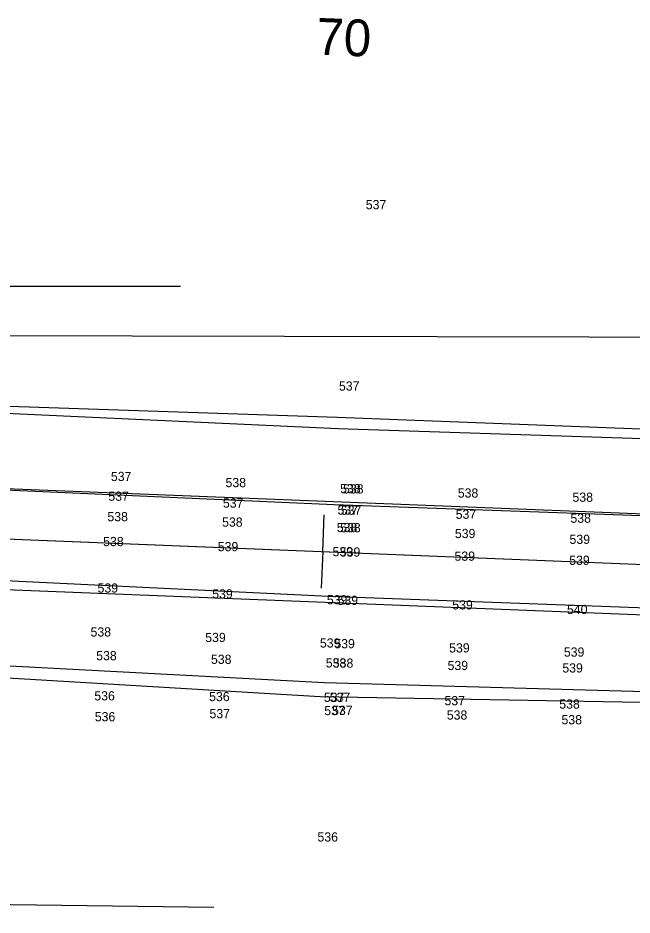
# Model space of a CAD drawing. Extents: x 1787461 to 1970323, y 938412 to 1118748.
# Drawn here: x 1968611.9 to 1968745.6, y 1117839 to 1118034.2 of the extents above; entities that cross this region are included whole.
import ezdxf

# ---------------------------------------------------------------- set-up
doc = ezdxf.new("R2010")
doc.units = 0
for name, color, linetype in [('Default', 7, 'Continuous'), ('HHA ADDITIONAL XSs', 7, 'Continuous'), ('Level 1', 7, 'Continuous'), ('RD_EX_DV_Prop', 7, 'Continuous'), ('RD_EX_Fence_Other', 7, 'Continuous'), ('RD_EX_Road', 7, 'Continuous'), ('RD_EX_VEG', 7, 'Continuous'), ('RD_HC_CL', 7, 'Continuous'), ('RD_HC_Data_Tic', 7, 'Continuous'), ('RD_HC_TX_Sta50', 7, 'Continuous'), ('RD_PD_Final_TrvlWay', 7, 'Continuous')]:
    doc.layers.add(name, color=color, linetype=linetype)

msp = doc.modelspace()

# ---------------------------------------------------------------- linework, layer by layer
at = {"layer": 'HHA ADDITIONAL XSs'}
msp.add_lwpolyline([(1969266.55, 1117963.61), (1967907.56, 1117966.55), (1967403.98, 1117771.66), (1967075.57, 1117641.84)], dxfattribs=at)
at = {"layer": 'Level 1'}
for points in [[(1968647.29, 1117975.82), (1967967.92, 1117975.82), (1967727.47, 1117916.63), (1966985.13, 1117603.01)], [(1968654.57, 1117840.68), (1968058.24, 1117848.48), (1967686.38, 1117740.3), (1966964.76, 1117453.35)]]:
    msp.add_lwpolyline(points, dxfattribs=at)
at = {"layer": 'RD_EX_DV_Prop'}
msp.add_line((1968370.12, 1117930.34), (1969277.79, 1117894.3), dxfattribs=at)
at = {"layer": 'RD_EX_Fence_Other'}
for points in [[(1968536.3, 1117952.23), (1968681.42, 1117947.34), (1968783.46, 1117943.44), (1968890.68, 1117939.26), (1968990.9, 1117933.42), (1969093.99, 1117930.77), (1969190.99, 1117925.01), (1969281.24, 1117923.59)], [(1968579.94, 1117894.82), (1968678.66, 1117889.64), (1968779.4, 1117886.8), (1968885.65, 1117881.12), (1968982.76, 1117877.17), (1969084.96, 1117872.96), (1969186.26, 1117869.55), (1969289.22, 1117863.98)]]:
    msp.add_lwpolyline(points, dxfattribs=at)
at = {"layer": 'RD_EX_Road'}
for points in [[(1968529.31, 1117935.06), (1968680.74, 1117928.37), (1968782, 1117924.72), (1968887.41, 1117920.79), (1968989.99, 1117916.45), (1969090.76, 1117912.42), (1969189.86, 1117908.01), (1969282.04, 1117904.78)], [(1968526.59, 1117915.77), (1968679.57, 1117908.43), (1968780.48, 1117904.73), (1968886.63, 1117901.2), (1968987.42, 1117897.59), (1969088.87, 1117892.19), (1969188.08, 1117888.4), (1969281.71, 1117884.78)]]:
    msp.add_lwpolyline(points, dxfattribs=at)
at = {"layer": 'RD_EX_VEG'}
for points in [[(1968535.19, 1117951.62), (1968681.64, 1117944.89), (1968783.26, 1117941.54), (1968890.11, 1117938.32), (1968991.04, 1117932.18), (1969094.36, 1117929.93), (1969190.81, 1117923.37), (1969281.69, 1117922.69)], [(1968580.4, 1117892.39), (1968677.7, 1117886.58), (1968780.39, 1117884.76), (1968885.66, 1117879.53), (1968982.9, 1117878.1), (1969085.82, 1117874.51), (1969187.45, 1117870.95), (1969289.3, 1117866.04)]]:
    msp.add_lwpolyline(points, dxfattribs=at)
at = {"layer": 'RD_HC_CL'}
msp.add_line((1968119.1, 1117940.3), (1969277.79, 1117894.3), dxfattribs=at)
at = {"layer": 'RD_HC_Data_Tic'}
for q in [(1968678.58, 1117926.1), (1968677.94, 1117910.11)]:
    msp.add_line((1968678.26, 1117918.11), q, dxfattribs=at)
at = {"layer": 'RD_PD_Final_TrvlWay'}
for p, q in [((1968478.85, 1117937.03), (1969278.22, 1117905.3)), ((1968477.98, 1117915.05), (1969277.35, 1117883.31))]:
    msp.add_line(p, q, dxfattribs=at)

# ---------------------------------------------------------------- texts
at = {"layer": 'Default'}
for s, p in [('537', (1968687.63, 1117992.6)), ('537', (1968681.79, 1117953.13)), ('537', (1968632.13, 1117933.45)), ('538', (1968657.09, 1117932.12)), ('538', (1968682.05, 1117930.79)), ('538', (1968682.68, 1117930.75)), ('537', (1968631.57, 1117929.16)), ('538', (1968707.66, 1117929.85)), ('538', (1968732.64, 1117928.94)), ('537', (1968656.52, 1117927.66)), ('538', (1968631.37, 1117924.7)), ('537', (1968681.48, 1117926.15)), ('537', (1968682.22, 1117926.11)), ('537', (1968707.21, 1117925.24)), ('538', (1968656.35, 1117923.52)), ('538', (1968732.19, 1117924.37)), ('538', (1968681.32, 1117922.34)), ('538', (1968682.06, 1117922.3)), ('539', (1968707.03, 1117921.04)), ('538', (1968630.44, 1117919.29)), ('539', (1968731.99, 1117919.77)), ('539', (1968655.41, 1117918.19)), ('539', (1968680.39, 1117917.08)), ('539', (1968681.97, 1117917.01)), ('539', (1968706.95, 1117916.11)), ('539', (1968731.93, 1117915.21)), ('539', (1968629.23, 1117909.18)), ('539', (1968654.19, 1117907.9)), ('539', (1968679.16, 1117906.62)), ('539', (1968681.48, 1117906.5)), ('539', (1968706.46, 1117905.51)), ('540', (1968731.44, 1117904.51)), ('538', (1968627.7, 1117899.62)), ('539', (1968652.67, 1117898.42)), ('539', (1968677.64, 1117897.22)), ('539', (1968680.79, 1117897.07)), ('539', (1968705.78, 1117896.15)), ('538', (1968628.93, 1117894.46)), ('538', (1968653.92, 1117893.67)), ('539', (1968730.76, 1117895.24)), ('538', (1968678.91, 1117892.89)), ('538', (1968680.45, 1117892.84)), ('539', (1968705.44, 1117892.32)), ('539', (1968730.43, 1117891.79)), ('536', (1968628.52, 1117885.72)), ('536', (1968653.52, 1117885.56)), ('537', (1968678.51, 1117885.4)), ('537', (1968679.78, 1117885.39)), ('537', (1968704.77, 1117884.66)), ('538', (1968729.76, 1117883.93)), ('537', (1968653.6, 1117881.84)), ('537', (1968678.59, 1117882.51)), ('537', (1968680.3, 1117882.55)), ('536', (1968628.62, 1117881.17)), ('538', (1968705.27, 1117881.54)), ('538', (1968730.25, 1117880.52)), ('536', (1968677.11, 1117855.01))]:
    msp.add_text(s, height=2, dxfattribs=at).set_placement(p)
at = {"layer": 'RD_HC_TX_Sta50'}
msp.add_text('70', height=8, rotation=357.7266, dxfattribs=at).set_placement((1968676.75, 1118026.25))

doc.saveas('drawing.dxf')
